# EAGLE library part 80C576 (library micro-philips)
8051 -compatible 8-bit Microcontroller
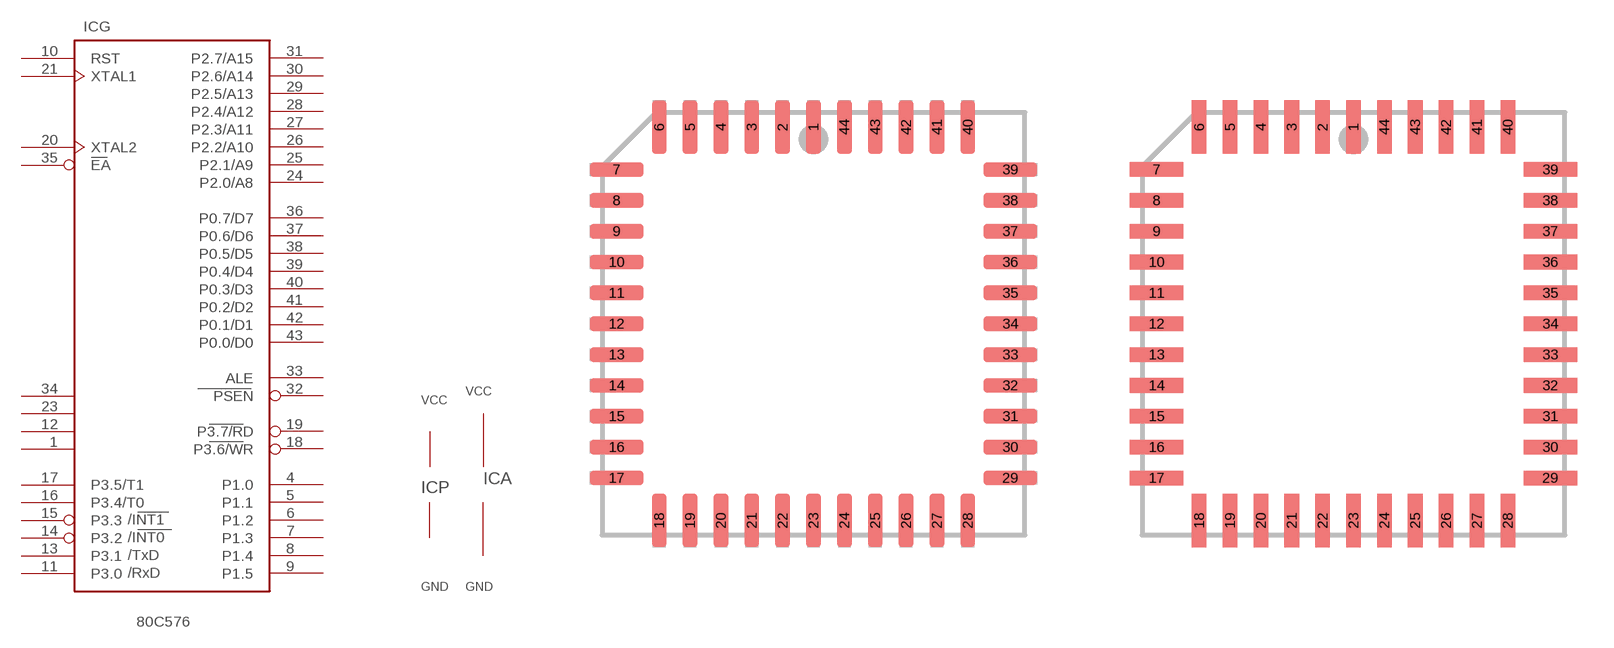
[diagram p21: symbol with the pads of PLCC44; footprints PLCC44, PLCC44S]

Designator prefix IC; gates P=PWR2 A=PWRA G=8XC576

## 80C576SMD (OC_FARNELL: unknown; OC_NEWARK: unknown)  [PLCC44]
1  G:NC  nc
2  A:AVCC  pwr
3  A:AGND  pwr
4  G:P1.0
5  G:P1.1
6  G:P1.2
7  G:P1.3
8  G:P1.4
9  G:P1.5
10  G:RST  in
11  G:P3.0
12  G:NC  nc
13  G:P3.1
14  G:P3.2
15  G:P3.3
16  G:P3.4/T0
17  G:P3.5/T1
18  G:P3.6/WR
19  G:P3.7/RD
20  G:XTAL2  in
21  G:XTAL1  in
22  P:GND  pwr
23  G:NC  nc
24  G:P2.0/A8
25  G:P2.1/A9
26  G:P2.2/A10
27  G:P2.3/A11
28  G:P2.4/A12
29  G:P2.5/A13
30  G:P2.6/A14
31  G:P2.7/A15
32  G:PSEN  out
33  G:ALE  out
34  G:NC  nc
35  G:EA  in
36  G:P0.7/D7
37  G:P0.6/D6
38  G:P0.5/D5
39  G:P0.4/D4
40  G:P0.3/D3
41  G:P0.2/D2
42  G:P0.1/D1
43  G:P0.0/D0
44  P:VCC  pwr

## 80C576S (OC_FARNELL: unknown; OC_NEWARK: unknown)  [PLCC44S]
Pads as for PLCC44

## Footprint PLCC44 (pad centres in mm)
PLASTIC LEADED CHIP CARRIER square
smd 0.6 x 2.2: 1 0,6.83; 2 -1.27,6.83; 3 -2.54,6.83; 4 -3.81,6.83; 5 -5.08,6.83; 6 -6.35,6.83; 18 -6.35,-9.37; 19 -5.08,-9.37; 20 -3.81,-9.37; 21 -2.54,-9.37; 22 -1.27,-9.37; 23 0,-9.37; 24 1.27,-9.37; 25 2.54,-9.37; 26 3.81,-9.37; 27 5.08,-9.37; 28 6.35,-9.37; 40 6.35,6.83; 41 5.08,6.83; 42 3.81,6.83; 43 2.54,6.83; 44 1.27,6.83
smd 2.2 x 0.6: 7 -8.1,5.08; 8 -8.1,3.81; 9 -8.1,2.54; 10 -8.1,1.27; 11 -8.1,0; 12 -8.1,-1.27; 13 -8.1,-2.54; 14 -8.1,-3.81; 15 -8.1,-5.08; 16 -8.1,-6.35; 17 -8.1,-7.62; 29 8.1,-7.62; 30 8.1,-6.35; 31 8.1,-5.08; 32 8.1,-3.81; 33 8.1,-2.54; 34 8.1,-1.27; 35 8.1,0; 36 8.1,1.27; 37 8.1,2.54; 38 8.1,3.81; 39 8.1,5.08

## Footprint PLCC44S (pad centres in mm)
PLASTIC LEADED CHIP CARRIER square
smd 0.6 x 2.2: 1 0,8.1; 2 -1.27,8.1; 3 -2.54,8.1; 4 -3.81,8.1; 5 -5.08,8.1; 6 -6.35,8.1; 18 -6.35,-8.1; 19 -5.08,-8.1; 20 -3.81,-8.1; 21 -2.54,-8.1; 22 -1.27,-8.1; 23 0,-8.1; 24 1.27,-8.1; 25 2.54,-8.1; 26 3.81,-8.1; 27 5.08,-8.1; 28 6.35,-8.1; 40 6.35,8.1; 41 5.08,8.1; 42 3.81,8.1; 43 2.54,8.1; 44 1.27,8.1
smd 2.2 x 0.6: 7 -8.1,6.35; 8 -8.1,5.08; 9 -8.1,3.81; 10 -8.1,2.54; 11 -8.1,1.27; 12 -8.1,0; 13 -8.1,-1.27; 14 -8.1,-2.54; 15 -8.1,-3.81; 16 -8.1,-5.08; 17 -8.1,-6.35; 29 8.1,-6.35; 30 8.1,-5.08; 31 8.1,-3.81; 32 8.1,-2.54; 33 8.1,-1.27; 34 8.1,0; 35 8.1,1.27; 36 8.1,2.54; 37 8.1,3.81; 38 8.1,5.08; 39 8.1,6.35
